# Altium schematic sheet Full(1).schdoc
size 305 x 190 mm
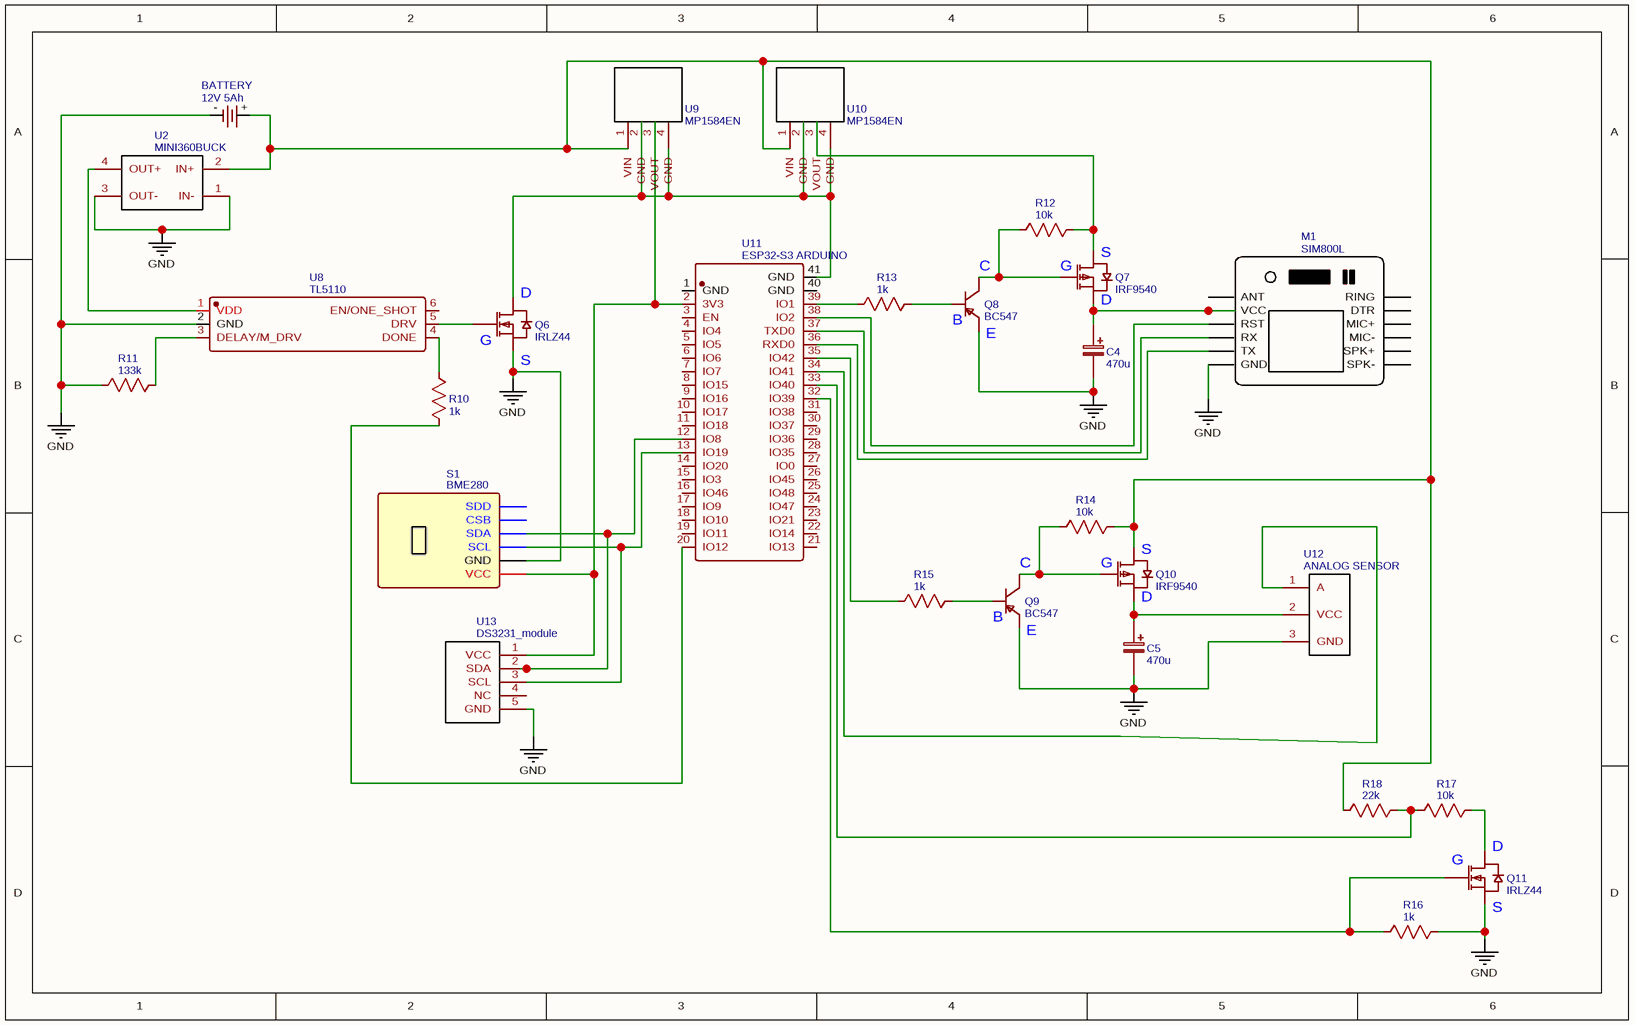
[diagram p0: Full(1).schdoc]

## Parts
BATTERY  12V 5Ah  [BATTERY-SMD-MY-2032]
C4  470u  [CASE-A_3216]
C5  470u  [CASE-A_3216]
M1  SIM800L  [SIM800LMODULE_SIM800LMODULE]
Q6  IRLZ44  [TO-220-3_L10.0-W4.5-P2.54-T]
Q7  IRF9540  [TO-263-2_L10.0-W9.1-P5.08-LS15.2-BR]
Q8  BC547  [SOT-23-3_L2.9-W1.6-P1.90-LS2.8-TR-CW]
Q9  BC547  [SOT-23-3_L2.9-W1.6-P1.90-LS2.8-TR-CW]
Q10  IRF9540  [TO-263-2_L10.0-W9.1-P5.08-LS15.2-BR]
Q11  IRLZ44  [TO-220-3_L10.0-W4.5-P2.54-T]
R10  1k  [R0603]
R11  133k  [R0603]
R12  10k  [R0603]
R13  1k  [R0603]
R14  10k  [R0603]
R15  1k  [R0603]
R16  1k  [R0603]
R17  10k  [R0603]
R18  22k  [R0603]
S1  BME280  [BME280]
U2  MINI360BUCK  [MINI360BUCK]
U8  TL5110  [TSOT-23-6_L2.9-W1.6-P0.95-LS2.8-BR]
U9  MP1584EN  [MP1584EN]
U10  MP1584EN  [MP1584EN]
U11  ESP32-S3 ARDUINO  [WIRELM-SMD_ESP32-S3-WROOM-1U]
U12  ANALOG SENSOR  [ANALOG SENSOR V1]
U13  DS3231_module  [DS3231]

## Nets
GND: BATTERY.-(BAT-) C4.2 C5.2 M1.6(GND) Q6.3(S) Q8.1(E) Q9.1(E) Q11.3(S) R11.2 R16.2 S1.2(GND) U2.1(IN-) U2.3(OUT-) U8.2(GND) U12.3(GND) U13.5(GND)
NetBATTERY_+: BATTERY.+(BAT+) Q10.4(D) R14.1 R18.1 U2.2(IN+)
NetC4_1: C4.1 M1.2(VCC) Q7.3(S)
NetC5_1: C5.1 Q10.3(S) U12.2(VCC)
NetM1_3: M1.3(RST) U11.38(IO2)
NetM1_4: M1.4(RX) U11.37(TXD0)
NetM1_5: M1.5(TX) U11.36(RXD0)
NetQ6_1: Q6.1(G) U8.5(DRV)
NetQ6_2: Q6.2(D) U9.2(GND) U10.2(GND) U11.41(GND)
NetQ7_1: Q7.1(G) Q8.3(C) R12.2
NetQ7_4: Q7.4(D) R12.1 U10.3(VOUT)
NetQ8_2: Q8.2(B) R13.2
NetQ9_2: Q9.2(B) R15.2
NetQ9_3: Q9.3(C) Q10.1(G) R14.2
NetQ11_1: Q11.1(G) R16.1 U11.32(IO39)
NetQ11_2: Q11.2(D) R17.2
NetR10_1: R10.1 U8.4(DONE)
NetR10_2: R10.2 U11.20(IO12)
NetR11_1: R11.1 U8.3(DELAY/M_DRV)
NetR13_1: R13.1 U11.39(IO1)
NetR15_1: R15.1 U11.35(IO42)
NetR17_1: R17.1 R18.2 U11.33(IO40)
NetS1_1: S1.1(VCC) U9.3(VOUT) U11.2(3V3) U13.1(VCC)
NetS1_3: S1.3(SCL) U11.13(IO19) U13.3(SCL)
NetS1_4: S1.4(SDA) U11.12(IO8) U13.2(SDA)
NetU2_4: U2.4(OUT+) U8.1(VDD)
NetU11_34: U11.34(IO41) U12.1(A)

Not connected (* = marked no-connect by the designer): M1 1(ANT) 7(SPK-) 8(SPK+) 9(MIC-) 10(MIC+) 11(DTR) 12(RING); S1 5(CSB) 6(SDD); U8 6(EN/ONE_SHOT); U9 1(VIN) 4(GND); U10 1(VIN) 4(GND); U11 1(GND) 3(EN) 4(IO4) 5(IO5) 6(IO6) 7(IO7) 8(IO15) 9(IO16) 10(IO17) 11(IO18) 14(IO20) 15(IO3) 16(IO46) 17(IO9) 18(IO10) 19(IO11) 21(IO13) 22(IO14) 23(IO21) 24(IO47) 25(IO48) 26(IO45) 27(IO0) 28(IO35) 29(IO36) 30(IO37) 31(IO38) 40(GND); U13 4(NC)

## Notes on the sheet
- (near Q6) D
- (near Q8) C
- (near Q7) G
- (near Q7) D
- (near Q7) S
- (near Q6) G
- (near Q6) S
- (near Q8) B
- (near Q8) E
- (near Q9) C
- (near Q10) G
- (near Q10) S
- (near Q9) B
- (near Q9) E
- (near Q10) D
- (near Q11) G
- (near Q11) D
- (near Q11) S

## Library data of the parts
BATTERY = 12V 5Ah: Manufacturer: MYOUNG(美阳); Manufacturer Part: MY-2032-10; Contributor: lcsc
C4 C5 = 470u: nameAlias: Value(F); Contributor: LCEDA_Lib
M1 = SIM800L: Contributor: sharad.rask
Q6 Q11 = IRLZ44: Manufacturer: Infineon(英飞凌); Manufacturer Part: IRLZ44NPBF
Q7 Q10 = IRF9540: Manufacturer: IR; Manufacturer Part: IRF5210STRLPBF; Paste Type: expand; Contributor: LCEDA_Lib
Q8 Q9 = BC547: Manufacturer: KEC; Manufacturer Part: 2N3906S-RTK/PS; Contributor: LCEDA_Lib
R10 R13 R15 R16 = 1k: nameAlias: Value(Ω); Contributor: LCEDA_Lib
R11 = 133k: nameAlias: Value(Ω); Contributor: LCEDA_Lib
R12 R14 R17 = 10k: nameAlias: Value(Ω); Contributor: LCEDA_Lib
R18 = 22k: nameAlias: Value(Ω); Contributor: LCEDA_Lib
U2 = MINI360BUCK: Contributor: Andrey Fedorov; sourceId: FRLFXR8qI
U8 = TL5110: Manufacturer: TI(德州仪器); Manufacturer Part: TPL5110DDCR; Contributor: lcsc; nameAlias: Value
U9 U10 = MP1584EN: Contributor: babeinlovexd
U11 = ESP32-S3 ARDUINO: Manufacturer: null; Manufacturer Part: ESP32-S3-WROOM-1U; Contributor: lcsc
U12 = ANALOG SENSOR: Contributor: utbahR
U13 = DS3231_module: Contributor: retret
